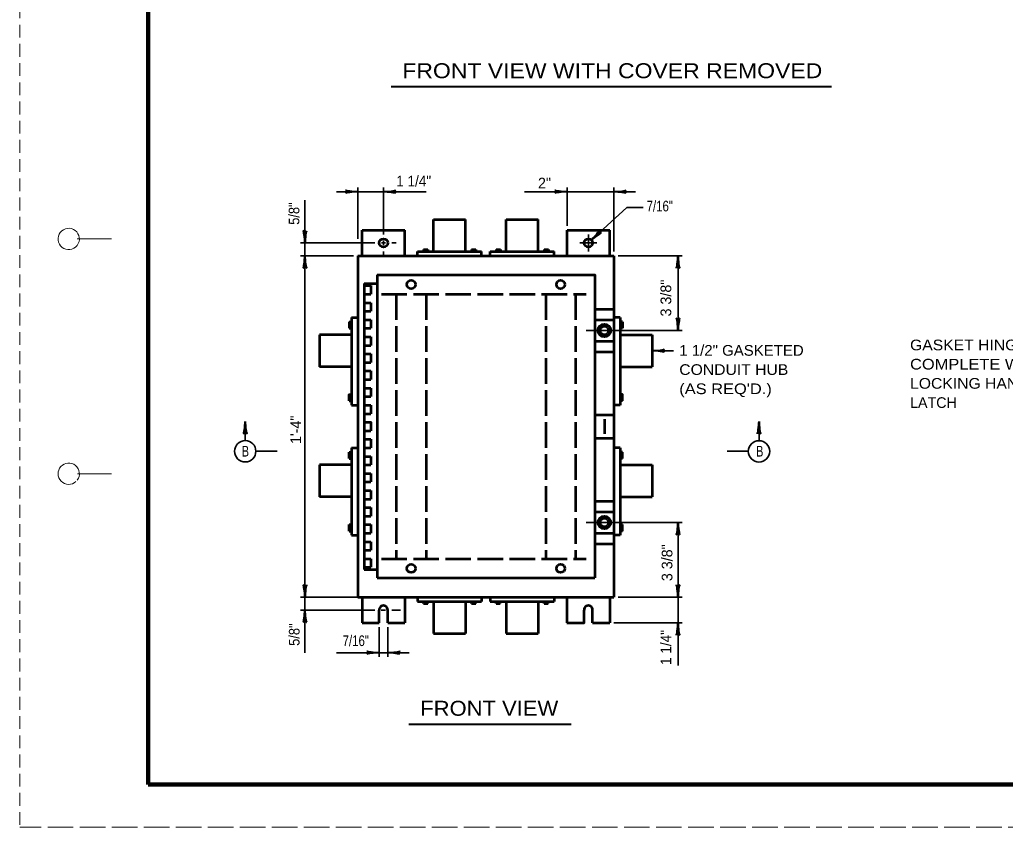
# Model space of a CAD drawing. Extents: x -1 to 679, y 0 to 440.
# Drawn here: x -1.3 to 229.6, y 0.4 to 189.6 of the extents above; entities that cross this region are included whole.
import ezdxf

# ---------------------------------------------------------------- set-up
doc = ezdxf.new("R2010")
doc.units = 0
doc.linetypes.add('LONG_DASHED', pattern=[7.5, 6, -1.5])
doc.linetypes.add('MEDIUM_DASHED', pattern=[4.5, 3, -1.5])
doc.layers.add('1', color=7, linetype='Continuous', lineweight=53)
doc.layers.add('61', color=7, linetype='Continuous', lineweight=35)

msp = doc.modelspace()

# ---------------------------------------------------------------- linework, layer by layer
at = {"layer": '1', "linetype": 'MEDIUM_DASHED', "lineweight": 13}
msp.add_line((-1.237, 440.398), (-1.297, 0.358), dxfattribs=at)
at = {"layer": '1', "lineweight": 40}
for p, q in [((85.68, 173.91), (188.889, 173.91)), ((89.888, 24.53), (127.89, 24.53))]:
    msp.add_line(p, q, dxfattribs=at)
at = {"layer": '1', "lineweight": 35}
for p, q in [((77.914, 138.268), (77.914, 150.268)), ((83.914, 150.268), (83.914, 139.266)), ((126.914, 141.268), (126.914, 150.268)), ((137.914, 135.268), (137.914, 150.268)), ((65.514, 134.268), (65.514, 147.268)), ((131.914, 139.264), (131.914, 135.264)), ((64.514, 137.268), (81.906, 137.268)), ((83.414, 137.268), (84.414, 137.268)), ((83.914, 137.768), (83.914, 136.768)), ((85.906, 137.268), (86.914, 137.268)), ((129.916, 137.268), (133.916, 137.268)), ((76.914, 134.268), (64.514, 134.268)), ((65.514, 134.268), (65.514, 54.268)), ((83.914, 135.266), (83.914, 134.499)), ((153.914, 134.268), (138.914, 134.268)), ((152.914, 134.268), (152.914, 116.768)), ((153.914, 116.768), (131.414, 116.768)), ((151.884, 112.018), (146.884, 112.018)), ((51.518, 90.959), (51.518, 95.447)), ((171.888, 90.941), (171.888, 95.447)), ((59.018, 88.447), (54.023, 88.447)), ((164.388, 88.447), (169.38, 88.447)), ((153.914, 71.768), (131.414, 71.768)), ((152.914, 54.268), (152.914, 71.768)), ((77.914, 54.268), (64.514, 54.268)), ((153.914, 54.268), (138.914, 54.268)), ((81.903, 51.268), (64.514, 51.268)), ((84.403, 51.268), (83.403, 51.268)), ((87.903, 51.268), (85.903, 51.268)), ((82.903, 47.271), (82.903, 40.271)), ((84.903, 47.271), (84.903, 40.271)), ((137.903, 48.271), (153.914, 48.271))]:
    msp.add_line(p, q, dxfattribs=at)
at = {"layer": '1'}
for p, q in [((95.664, 135.268), (95.664, 142.768)), ((95.664, 142.768), (103.164, 142.768)), ((103.164, 135.268), (103.164, 142.768)), ((112.664, 135.268), (112.664, 142.768)), ((112.664, 142.768), (120.164, 142.768)), ((120.164, 135.268), (120.164, 142.768)), ((78.914, 134.268), (78.914, 140.268)), ((78.914, 140.268), (88.914, 140.268)), ((88.914, 134.268), (88.914, 140.268)), ((126.914, 134.268), (126.914, 140.268)), ((126.914, 140.268), (136.914, 140.268)), ((136.914, 134.268), (136.914, 140.268)), ((77.914, 134.268), (137.914, 134.268)), ((77.914, 134.268), (77.914, 54.268)), ((91.914, 134.268), (91.914, 135.268)), ((91.914, 135.268), (95.664, 135.268)), ((93.289, 135.768), (93.289, 135.268)), ((93.289, 135.768), (94.289, 135.768)), ((94.289, 135.768), (94.289, 135.268)), ((104.539, 135.768), (104.539, 135.268)), ((104.539, 135.768), (105.539, 135.768)), ((105.539, 135.768), (105.539, 135.268)), ((106.914, 134.268), (106.914, 135.268)), ((108.914, 134.268), (108.914, 135.268)), ((108.914, 135.268), (112.664, 135.268)), ((110.289, 135.768), (110.289, 135.268)), ((110.289, 135.768), (111.289, 135.768)), ((111.289, 135.768), (111.289, 135.268)), ((121.539, 135.768), (121.539, 135.268)), ((121.539, 135.768), (122.539, 135.768)), ((122.539, 135.768), (122.539, 135.268)), ((123.914, 134.268), (123.914, 135.268)), ((137.914, 134.268), (137.914, 54.268)), ((82.414, 129.768), (82.414, 58.768)), ((79.414, 127.768), (79.414, 60.768)), ((79.414, 127.768), (82.414, 127.768)), ((79.414, 127.268), (80.914, 127.268)), ((80.914, 127.268), (80.914, 125.268)), ((79.414, 125.268), (80.914, 125.268)), ((79.414, 123.268), (80.914, 123.268)), ((80.914, 123.268), (80.914, 121.268)), ((79.414, 121.268), (80.914, 121.268)), ((133.414, 121.768), (137.914, 121.768)), ((75.914, 118.768), (75.914, 117.268)), ((75.914, 118.768), (76.414, 118.768)), ((76.414, 119.768), (76.414, 99.268)), ((76.414, 119.768), (77.914, 119.768)), ((79.414, 119.268), (80.914, 119.268)), ((80.914, 119.268), (80.914, 117.268)), ((133.414, 119.268), (137.914, 119.268)), ((139.384, 119.768), (137.884, 119.768)), ((139.384, 119.768), (139.384, 99.268)), ((139.884, 118.768), (139.384, 118.768)), ((139.884, 118.768), (139.884, 117.268)), ((76.414, 115.768), (68.914, 115.768)), ((68.914, 115.768), (68.914, 108.268)), ((75.914, 117.268), (76.414, 117.268)), ((79.414, 117.268), (80.914, 117.268)), ((139.884, 117.268), (139.384, 117.268)), ((139.384, 115.768), (146.884, 115.768)), ((146.884, 115.768), (146.884, 108.268)), ((79.414, 115.268), (80.914, 115.268)), ((79.414, 113.268), (80.914, 113.268)), ((80.914, 115.268), (80.914, 113.268)), ((133.414, 114.268), (137.914, 114.268)), ((79.414, 111.268), (80.914, 111.268)), ((80.914, 111.268), (80.914, 109.268)), ((133.414, 111.768), (137.914, 111.768)), ((79.414, 109.268), (80.914, 109.268)), ((76.414, 108.268), (68.914, 108.268)), ((79.414, 107.268), (80.914, 107.268)), ((80.914, 107.268), (80.914, 105.268)), ((139.384, 108.268), (146.884, 108.268)), ((79.414, 105.268), (80.914, 105.268)), ((79.414, 103.268), (80.914, 103.268)), ((80.914, 103.268), (80.914, 101.268)), ((75.914, 100.268), (76.414, 100.268)), ((79.414, 101.268), (80.914, 101.268)), ((139.884, 100.268), (139.384, 100.268)), ((76.414, 99.268), (77.914, 99.268)), ((79.414, 99.268), (80.914, 99.268)), ((79.414, 97.268), (80.914, 97.268)), ((80.914, 99.268), (80.914, 97.268)), ((133.414, 97.018), (137.914, 97.018)), ((139.384, 99.268), (137.884, 99.268)), ((135.664, 96.018), (135.664, 92.518)), ((79.414, 93.268), (80.914, 93.268)), ((79.414, 91.268), (80.914, 91.268)), ((80.914, 91.268), (80.914, 89.268)), ((133.414, 91.518), (137.914, 91.518)), ((75.914, 88.268), (76.414, 88.268)), ((75.914, 86.768), (75.914, 88.268)), ((76.414, 89.268), (76.414, 68.768)), ((76.414, 89.268), (77.914, 89.268)), ((79.414, 89.268), (80.914, 89.268)), ((139.384, 89.268), (137.884, 89.268)), ((139.384, 89.268), (139.384, 68.768)), ((139.884, 88.268), (139.384, 88.268)), ((139.884, 86.768), (139.884, 88.268)), ((75.914, 86.768), (76.414, 86.768)), ((79.414, 87.268), (80.914, 87.268)), ((80.914, 87.268), (80.914, 85.268)), ((139.884, 86.768), (139.384, 86.768)), ((76.414, 85.268), (68.914, 85.268)), ((68.914, 85.268), (68.914, 77.768)), ((79.414, 85.268), (80.914, 85.268)), ((79.414, 83.268), (80.914, 83.268)), ((80.914, 83.268), (80.914, 81.268)), ((139.384, 85.268), (146.884, 85.268)), ((146.884, 85.268), (146.884, 77.768)), ((79.414, 81.268), (80.914, 81.268)), ((79.414, 79.268), (80.914, 79.268)), ((80.914, 79.268), (80.914, 77.268)), ((76.414, 77.768), (68.914, 77.768)), ((79.414, 77.268), (80.914, 77.268)), ((133.414, 76.768), (137.914, 76.768)), ((139.384, 77.768), (146.884, 77.768)), ((79.414, 75.268), (80.914, 75.268)), ((80.914, 75.268), (80.914, 73.268)), ((133.414, 74.268), (137.914, 74.268)), ((79.414, 73.268), (80.914, 73.268)), ((75.914, 71.268), (76.414, 71.268)), ((75.914, 69.768), (75.914, 71.268)), ((75.914, 69.768), (76.414, 69.768)), ((79.414, 71.268), (80.914, 71.268)), ((79.414, 69.268), (80.914, 69.268)), ((80.914, 71.268), (80.914, 69.268)), ((133.414, 69.268), (137.914, 69.268)), ((139.884, 71.268), (139.384, 71.268)), ((139.884, 69.768), (139.384, 69.768)), ((139.884, 69.768), (139.884, 71.268)), ((76.414, 68.768), (77.914, 68.768)), ((79.414, 67.268), (80.914, 67.268)), ((80.914, 67.268), (80.914, 65.268)), ((139.384, 68.768), (137.884, 68.768)), ((79.414, 65.268), (80.914, 65.268)), ((133.414, 66.768), (137.914, 66.768)), ((79.414, 63.268), (80.914, 63.268)), ((80.914, 63.268), (80.914, 61.268)), ((79.414, 61.268), (80.914, 61.268)), ((79.414, 60.768), (82.414, 60.768)), ((82.414, 58.768), (133.414, 58.768)), ((77.914, 54.268), (137.914, 54.268)), ((78.903, 54.271), (78.903, 48.271)), ((88.903, 54.271), (88.903, 48.271)), ((91.903, 54.271), (91.903, 53.271)), ((91.903, 53.271), (95.653, 53.271)), ((93.278, 52.771), (93.278, 53.271)), ((94.278, 52.771), (94.278, 53.271)), ((95.653, 53.271), (95.653, 45.771)), ((103.153, 53.271), (103.153, 45.771)), ((104.528, 52.771), (104.528, 53.271)), ((105.528, 52.771), (105.528, 53.271)), ((106.903, 54.271), (106.903, 53.271)), ((108.903, 54.271), (108.903, 53.271)), ((108.903, 53.271), (112.653, 53.271)), ((110.278, 52.771), (110.278, 53.271)), ((111.278, 52.771), (111.278, 53.271)), ((112.653, 53.271), (112.653, 45.771)), ((120.153, 53.271), (120.153, 45.771)), ((121.528, 52.771), (121.528, 53.271)), ((122.528, 52.771), (122.528, 53.271)), ((123.903, 54.271), (123.903, 53.271)), ((126.903, 54.271), (126.903, 48.271)), ((136.903, 54.271), (136.903, 48.271)), ((82.903, 48.271), (82.903, 51.268)), ((84.903, 48.271), (84.903, 51.268)), ((93.278, 52.771), (94.278, 52.771)), ((104.528, 52.771), (105.528, 52.771)), ((110.278, 52.771), (111.278, 52.771)), ((121.528, 52.771), (122.528, 52.771)), ((132.903, 48.271), (132.903, 51.268)), ((78.903, 48.271), (82.903, 48.271)), ((84.903, 48.271), (88.903, 48.271)), ((132.903, 48.271), (136.903, 48.271)), ((95.653, 45.771), (103.153, 45.771)), ((112.653, 45.771), (120.153, 45.771))]:
    msp.add_line(p, q, dxfattribs=at)
at = {"layer": '1', "linetype": 'LONG_DASHED'}
for p, q in [((83.414, 125.268), (131.414, 125.268)), ((86.914, 125.268), (86.914, 63.268)), ((93.914, 125.268), (93.914, 63.268)), ((121.914, 125.268), (121.914, 63.268)), ((128.914, 125.268), (128.914, 63.268)), ((83.414, 63.268), (131.414, 63.268))]:
    msp.add_line(p, q, dxfattribs=at)
at = {"layer": '1', "lineweight": 35}
for points in [[(72.914, 149.268), (77.914, 149.268), (83.914, 149.268), (93.914, 149.268)], [(116.914, 149.268), (126.914, 149.268), (137.914, 149.268), (142.914, 149.268)], [(132.606, 137.987), (140.952, 145.573), (144.714, 145.573)], [(65.514, 54.268), (65.514, 51.268), (65.514, 41.268)], [(152.914, 54.268), (152.914, 48.271), (152.914, 38.271)], [(72.903, 41.271), (82.903, 41.271), (84.903, 41.271), (89.903, 41.271)]]:
    msp.add_lwpolyline(points, dxfattribs=at)
at = {"layer": '1'}
for points in [[(95.664, 135.268), (103.164, 135.268), (106.914, 135.268)], [(112.664, 135.268), (120.164, 135.268), (123.914, 135.268)], [(82.414, 129.768), (133.414, 129.768), (133.414, 58.768)], [(75.914, 100.268), (75.914, 101.768), (76.414, 101.768)], [(139.884, 100.268), (139.884, 101.768), (139.384, 101.768)], [(79.414, 95.268), (80.914, 95.268), (80.914, 93.268)], [(95.653, 53.271), (103.153, 53.271), (106.903, 53.271)], [(112.653, 53.271), (120.153, 53.271), (123.903, 53.271)], [(126.903, 48.271), (130.903, 48.271), (130.903, 51.268)]]:
    msp.add_lwpolyline(points, dxfattribs=at)
for centre, radius in [((83.906, 137.266), 1), ((131.916, 137.264), 1), ((90.415, 127.52), 1), ((125.411, 127.519), 1), ((135.665, 116.767), 1.5), ((135.665, 116.767), 1), ((135.665, 71.769), 1.5), ((135.665, 71.769), 1), ((90.413, 61.016), 1), ((125.417, 61.019), 1)]:
    msp.add_circle(centre, radius, dxfattribs=at)
at = {"layer": '1', "lineweight": 35}
for centre in [(51.523, 88.459), (171.88, 88.441)]:
    msp.add_circle(centre, 2.5, dxfattribs=at)
at = {"layer": '1'}
for centre in [(83.903, 51.303), (131.903, 51.303)]:
    msp.add_arc(centre, 1.001, 358.01335, 181.98664, dxfattribs=at)
at = {"layer": '1', "lineweight": 40}
for centre, major_axis, ratio, start_param, end_param in [((76.823, 148.992), (1.786, 0.156), 0.122415, 0.8963533, 3.1415927), ((76.794, 149.48), (1.756, -0.176), 0.07063, 3.1407148, 5.41811), ((85.005, 149.544), (-1.786, -0.156), 0.122415, 0.8963533, 3.1415927), ((85.035, 149.056), (-1.756, 0.176), 0.07063, 3.1407148, 5.41811), ((125.823, 148.992), (1.786, 0.156), 0.122415, 0.8963533, 3.1415927), ((125.823, 148.992), (1.786, 0.156), 0.122415, 0.8963533, 3.1415927), ((125.794, 149.48), (1.756, -0.176), 0.07063, 3.1407148, 5.41811), ((125.794, 149.48), (1.756, -0.176), 0.07063, 3.1407148, 5.41811), ((139.005, 149.544), (-1.786, -0.156), 0.122415, 0.8963533, 3.1415927), ((139.005, 149.544), (-1.786, -0.156), 0.122415, 0.8963533, 3.1415927), ((139.035, 149.056), (-1.756, 0.176), 0.07063, 3.1407148, 5.41811), ((139.035, 149.056), (-1.756, 0.176), 0.07063, 3.1407148, 5.41811), ((65.238, 138.359), (0.156, -1.786), 0.122415, 0.8963533, 3.1415927), ((65.726, 138.388), (-0.176, -1.756), 0.07063, 3.1407148, 5.41811), ((133.228, 138.926), (-1.216, -1.317), 0.122415, 0.8963533, 3.1415927), ((133.578, 138.584), (1.418, 1.051), 0.07063, 6.2823074, 8.5597026), ((65.302, 133.147), (0.176, 1.756), 0.07063, 3.1407148, 5.41811), ((65.79, 133.177), (-0.156, 1.786), 0.122415, 0.8963533, 3.1415927), ((152.702, 133.147), (0.176, 1.756), 0.07063, 3.1407148, 5.41811), ((152.702, 133.147), (0.176, 1.756), 0.07063, 3.1407148, 5.41811), ((153.19, 133.177), (-0.156, 1.786), 0.122415, 0.8963533, 3.1415927), ((153.19, 133.177), (-0.156, 1.786), 0.122415, 0.8963533, 3.1415927), ((152.638, 117.859), (0.156, -1.786), 0.122415, 0.8963533, 3.1415927), ((152.638, 117.859), (0.156, -1.786), 0.122415, 0.8963533, 3.1415927), ((153.126, 117.888), (-0.176, -1.756), 0.07063, 3.1407148, 5.41811), ((153.126, 117.888), (-0.176, -1.756), 0.07063, 3.1407148, 5.41811), ((148.004, 111.806), (-1.756, 0.176), 0.07063, 3.1407148, 5.41811), ((147.975, 112.294), (-1.786, -0.156), 0.122415, 0.8963533, 3.1415927), ((51.306, 94.327), (0.176, 1.756), 0.07063, 3.1407148, 5.41811), ((51.794, 94.356), (-0.156, 1.786), 0.122415, 0.8963533, 3.1415927), ((171.676, 94.327), (0.176, 1.756), 0.07063, 3.1407148, 5.41811), ((172.164, 94.356), (-0.156, 1.786), 0.122415, 0.8963533, 3.1415927), ((152.638, 70.677), (0.156, 1.786), 0.122415, 3.1415927, 5.386832), ((152.638, 70.677), (0.156, 1.786), 0.122415, 3.1415927, 5.386832), ((153.126, 70.647), (-0.176, 1.756), 0.07063, 0.8650754, 3.1424706), ((153.126, 70.647), (-0.176, 1.756), 0.07063, 0.8650754, 3.1424706), ((65.238, 55.359), (0.156, -1.786), 0.122415, 0.8963533, 3.1415927), ((65.726, 55.388), (-0.176, -1.756), 0.07063, 3.1407148, 5.41811), ((152.702, 55.388), (0.176, -1.756), 0.07063, 0.8650754, 3.1424706), ((152.702, 55.388), (0.176, -1.756), 0.07063, 0.8650754, 3.1424706), ((153.19, 55.359), (-0.156, -1.786), 0.122415, 3.1415927, 5.386832), ((153.19, 55.359), (-0.156, -1.786), 0.122415, 3.1415927, 5.386832), ((65.302, 50.147), (0.176, 1.756), 0.07063, 3.1407148, 5.41811), ((65.79, 50.177), (-0.156, 1.786), 0.122415, 0.8963533, 3.1415927), ((152.702, 47.15), (0.176, 1.756), 0.07063, 3.1407148, 5.41811), ((153.19, 47.18), (-0.156, 1.786), 0.122415, 0.8963533, 3.1415927), ((81.782, 41.482), (1.756, -0.176), 0.07063, 3.1407148, 5.41811), ((81.782, 41.482), (1.756, -0.176), 0.07063, 3.1407148, 5.41811), ((85.994, 41.547), (-1.786, -0.156), 0.122415, 0.8963533, 3.1415927), ((85.994, 41.547), (-1.786, -0.156), 0.122415, 0.8963533, 3.1415927), ((81.811, 40.994), (1.786, 0.156), 0.122415, 0.8963533, 3.1415927), ((81.811, 40.994), (1.786, 0.156), 0.122415, 0.8963533, 3.1415927), ((86.023, 41.059), (-1.756, 0.176), 0.07063, 3.1407148, 5.41811), ((86.023, 41.059), (-1.756, 0.176), 0.07063, 3.1407148, 5.41811)]:
    msp.add_ellipse(centre, major_axis=major_axis, ratio=ratio, start_param=start_param, end_param=end_param, dxfattribs=at)
at = {"layer": '61', "lineweight": 13}
for p, q in [((12.183, 138.218), (20.183, 138.218)), ((12.203, 83.198), (20.183, 83.198))]:
    msp.add_line(p, q, dxfattribs=at)
at = {"layer": '61', "lineweight": 158}
msp.add_line((667.823, 10.358), (28.763, 10.378), dxfattribs=at)
at = {"layer": '61', "linetype": 'LONG_DASHED', "lineweight": 13}
msp.add_line((678.763, 0.378), (-1.297, 0.358), dxfattribs=at)
at = {"layer": '61', "lineweight": 158}
msp.add_lwpolyline([(667.803, 430.398), (28.763, 430.398), (28.763, 10.378)], dxfattribs=at)
at = {"layer": '61', "lineweight": 13}
for centre, start, end in [((10.181, 138.199), 322.67175, 321.71615), ((10.181, 83.199), 323.13009, 312.31439)]:
    msp.add_arc(centre, 2.5, start, end, dxfattribs=at)

# ---------------------------------------------------------------- texts
at = {"layer": '1'}
for s, height, width, p in [('FRONT VIEW WITH COVER REMOVED', 3.5, 1.15, (88.325, 175.872)), ('1 1/4"', 2.5, 0.95, (86.894, 150.516)), ('7/16"', 2.5, 0.8, (145.559, 144.66)), ('1 1/2" GASKETED', 2.5, 1.05, (153.206, 110.845)), ('GASKET HINGED DOOR', 2.5, 1.1, (207.266, 112.113)), ('CONDUIT HUB', 2.5, 1.1, (153.206, 106.345)), ('COMPLETE WITH KEY', 2.5, 1.15, (207.266, 107.613)), ("(AS REQ'D.)", 2.5, 1.15, (153.206, 101.845)), ('LOCKING HANDLE AND', 2.5, 1.1, (207.266, 103.113)), ('B', 2.5, 0.75, (50.743, 87.219)), ('B', 2.5, 0.75, (171.232, 87.219)), ('7/16"', 2.5, 0.8, (74.348, 42.828)), ('FRONT VIEW', 3.5, 1.1, (92.533, 26.491))]:
    msp.add_text(s, height=height, dxfattribs=dict(at, width=width)).set_placement(p)
for s, p in [('2"', (120.109, 150.038)), ('LATCH', (207.266, 98.613))]:
    msp.add_text(s, height=2.5, dxfattribs=at).set_placement(p)
for s, width, p in [('5/8"', 0.9, (64.209, 141.52)), ('5/8"', 0.9, (64.254, 42.87)), ('1 1/4"', 0.95, (151.314, 38.391))]:
    msp.add_text(s, height=2.5, rotation=90, dxfattribs=dict(at, width=width)).set_placement(p)
for s, p in [('3 3/8"', (151.314, 120.052)), ('1\'-4"', (64.629, 90.166)), ('3 3/8"', (151.595, 58.034))]:
    msp.add_text(s, height=2.5, rotation=90, dxfattribs=at).set_placement(p)

doc.saveas('drawing.dxf')
